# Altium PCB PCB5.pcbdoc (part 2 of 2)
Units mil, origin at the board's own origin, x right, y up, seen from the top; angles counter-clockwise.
Board outline 5683.34 x 2704.79 mil, 4 copper layers (Top Layer, Inner1, Inner2, Bottom Layer); 104 components, 86 nets, 284 pads, 113 vias.
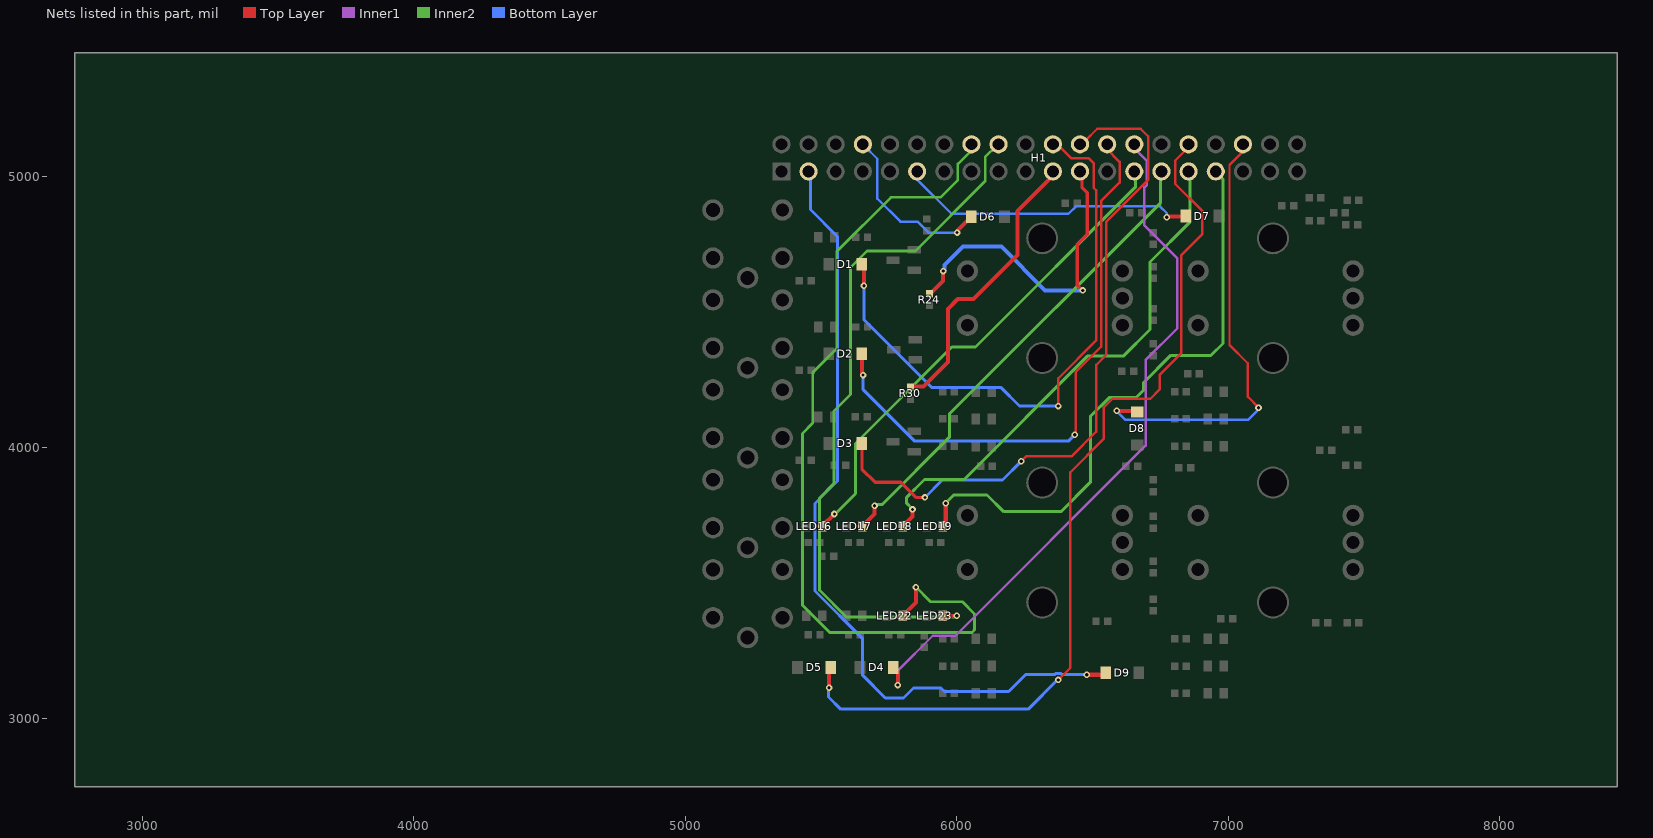
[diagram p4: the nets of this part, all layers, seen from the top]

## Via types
v1: diameter 24.02, hole 12.01, Top Layer to Bottom Layer, 86 vias
v2: diameter 25, hole 12, Top Layer to Bottom Layer, 7 vias
v3: diameter 33, hole 18, Top Layer to Bottom Layer, 6 vias
v4: diameter 25, hole 15, Top Layer to Bottom Layer, 5 vias
v5: diameter 30, hole 15, Top Layer to Bottom Layer, 3 vias
v6: diameter 30, hole 16, Top Layer to Bottom Layer, 3 vias
v7: diameter 28, hole 15, Top Layer to Bottom Layer, 1 vias
v8: diameter 35, hole 18, Top Layer to Bottom Layer, 1 vias
v9: diameter 22, hole 12, Top Layer to Bottom Layer, 1 vias

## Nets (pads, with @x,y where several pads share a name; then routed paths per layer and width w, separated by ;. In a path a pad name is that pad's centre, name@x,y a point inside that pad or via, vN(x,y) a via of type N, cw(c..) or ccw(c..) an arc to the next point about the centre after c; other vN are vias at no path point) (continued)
ROOM3_LED: H1.16 LED22.2 | length 3183.6
  Top Layer w15: LED22.2@5800.47,3380.07 5849.24,3428.84 v1(5849.24,3485.06)
  Inner2 w10: v1@5845.09,3489.42 5902.8,3431.71 6020.54,3431.71 6065.32,3386.93 6065.32,3328.61 6055.32,3318.61 5531.91,3318.61 5431.61,3418.91 5431.61,4051.86 5469.24,4089.49 5469.24,4275.54 5557.61,4363.91 5557.61,4721.82 5757.16,4921.37 5939.92,4921.37 6003.47,4984.92 6003.47,5044.16 6046.1,5086.79 H1.16@6046.1,5115.3
ROOM4_LED: H1.18 LED23.2 | length 2617
  Top Layer w15: LED23.2@5948.77,3380.07 v1(5999.24,3380.06)
  Inner2 w10: v1@5998.07,3375.58 5592.49,3375.58 5493.73,3474.34 5493.73,3814.24 5547.75,3868.26 5547.75,4134.26 5608.43,4194.93 5608.43,4663 5669.39,4723.97 5847.3,4723.97 6104.22,4980.89 6104.22,5069.46 6147.49,5112.73 H1.18@6147.49,5120.64
SINGLE_ROOM_LED: H1.21 R30.1 | length 1062.7
  Top Layer w15: R30.1@5827.41,4224.48 5876.42,4224.48 5966.62,4314.67 5966.62,4510.35 6003.32,4547.04 6061.03,4547.04 6222.71,4708.72 6222.71,4870.8 H1.21@6357.11,5005.2
SINGLE_SPK_LED: H1.23 R24.1 | length 1207
  Top Layer w12: H1.23@6446.98,5017.28 6460.68,5003.57 6460.68,4959.04 6480.71,4939.01 6480.71,4786.01 6443.81,4749.12 6443.81,4598.26 v1(6463.58,4578.49)
  Top Layer w15: R24.1@5899.68,4563.6 5949.49,4613.41 v1@5949.49,4652.94
  Bottom Layer w15: v1@5955.22,4654.39 5955.22,4671.96 6023.04,4739.78 6163.94,4739.78 6325.22,4578.49 v1(6463.58,4578.49)
  other v1: 5950.28,4649.78
SPK1_LED: H1.27 LED16.2 | length 1835.9
  Top Layer w15: LED16.2@5503.77,3710.07 5548.76,3755.06 v1(5549.24,3755.06)
  Inner2 w11: v1@5549.86,3753.01 5626.53,3829.67 5626.53,4014.74 5981.56,4369.78 6068.7,4369.78 6657.2,4958.28 H1.27@6657.2,5015.11
SPK2_LED: H1.29 LED17.2 | length 1772.1
  Top Layer w15: LED17.2@5652.1,3710.07 5696.99,3754.96 v1(5696.99,3785.06)
  Inner2 w11: v1@5694.74,3789.28 5724.09,3789.28 5972.24,4037.43 5972.24,4123.31 6750.79,4901.85 H1.29@6750.79,5013.13
SPK3_LED: H1.31 LED18.2 | length 1905.9
  Top Layer w15: LED18.2@5800.43,3710.07 5836.61,3746.25 v1(5836.61,3772.02)
  Inner2 w11: v1@5832.9,3776.82 5815.11,3794.61 5815.11,3816.62 5880.86,3882.37 6026.8,3882.37 6480.7,4336.28 6613.03,4336.28 6711.56,4434.8 6711.56,4683.35 6858.12,4829.91 H1.31@6858.12,5003.35
SPK4_LED: H1.33 LED19.2 | length 2200.2
  Top Layer w15: LED19.2@5948.77,3710.07 5959.24,3720.54 v1(5959.24,3795.06)
  Inner2 w11: v1@5961.72,3798.71 5988.4,3825.4 6111.14,3825.4 6172.81,3763.73 6383.9,3763.73 6491.82,3871.65 6491.82,4113.84 6563.03,4185.05 6661.8,4185.05 6688.24,4211.48 6688.24,4239.89 6788,4339.65 6936.51,4339.65 6980.05,4383.2 6980.9,4987.59 H1.33@6955.16,5013.33
SW_ALL_ROOM: D1.1 H1.22 | length 2191.5
  Top Layer w9: H1.22@6357.42,5127.5 6359.17,5127.5 6420.62,5066.05 6485.51,5066.05 6503.94,5047.62 6503.94,4956.83 6512.94,4947.83 6512.94,4394.11 6373.81,4254.98 v1(6373.81,4152.52)
  Top Layer w15: D1.1@5650.26,4675.06 5657.64,4667.68 v1(5657.64,4596.25)
  Bottom Layer w11: v1(5657.64,4596.25) 5657.64,4470.61 5906.7,4221.55 6161.48,4221.55 6230.52,4152.52 v1(6373.81,4152.52)
SW_BASS: D8.1 H1.36 | length 1659
  Top Layer w9: H1.36@7050.28,5113.12 7046.32,5109.17 7046.32,5083.06 7004.45,5041.18 7004.45,4377.42 7071.43,4310.44 7071.43,4187.23 v1@7110.76,4147.89
  Top Layer w15: v1(6588.56,4135.05) 6654.97,4135.05 D8.1@6660.51,4129.51
  Bottom Layer w10: v1(6588.56,4135.05) 6621.77,4101.84 7073.2,4101.84 v1@7114.32,4142.95
  other v1: 7111.15,4146.9
SW_CHG_ROOM: D5.1 H1.32 | length 3359.7
  Top Layer w9: v1(6373.7,3143.87) 6417.78,3187.95 6417.78,3908.57 6540.44,4031.23 6540.44,4146.26 6573.98,4179.8 6713.01,4179.8 6747,4213.79 6747,4267.74 6827.03,4347.77 6827.03,4709.08 6904.6,4786.65 6904.6,4871.08 6804.01,4971.67 6804.01,5056.47 6846.93,5099.39 6846.93,5116.31 H1.32@6849.74,5119.12
  Top Layer w15: v1(5529.24,3115.06) 5529.24,3184.04 D5.1@5535.26,3190.06
  Bottom Layer w11: v1@5527.36,3117.78 5527.36,3081.02 5572.42,3035.95 6262.62,3035.95 v1@6371.73,3145.06
SW_CHG_SPK: D4.1 H1.28 | length 2620.8
  Top Layer w15: D4.1@5765.26,3190.06 5782.56,3172.76 v1(5782.56,3125.06)
  Inner1 w9: v1@5775.9,3128.91 5783.81,3136.82 5783.81,3179.11 5911.2,3306.5 5994.7,3306.5 6695.12,4006.92 6695.12,4322.23 6812.39,4439.5 6812.39,4696.68 6690.93,4818.13 6690.93,4957.98 6699.93,4966.98 6699.93,5055.23 6648.43,5106.73 H1.28@6648.43,5119.46 ; v1@5777.42,3124.4 v1@5777.42,3128.91
SW_EXTRA: D9.1 H1.3 | length 2972.4
  Top Layer w15: v1(6478.17,3162.95) 6541.1,3162.95 D9.1@6548.22,3170.06
  Bottom Layer w11: H1.3@5461.13,5002.11 5461.13,4876.3 5560.75,4776.69 5560.75,3877.27 5477.14,3793.67 5477.14,3471.69 5653.19,3295.65 5653.19,3160.93 5736.68,3077.43 5803.67,3077.43 5840.05,3113.81 5941.5,3113.81 5954.45,3100.87 6190.8,3100.87 6252.87,3162.95 6359.55,3162.95 6363.97,3167.36 6383.43,3167.36 6387.85,3162.95 v1(6478.17,3162.95)
SW_SINGLE_ROOM: D3.1 H1.24 | length 2543.7
  Top Layer w9: v1(6237.32,3949.47) 6255.11,3967.26 6422.4,3967.26 6513.46,4058.32 6513.46,4304.14 6549.99,4340.67 6549.99,4830.62 6704.7,4985.34 6704.68,5146.36 6677.08,5173.96 6517.37,5173.96 6472.28,5128.86 H1.24@6459.55,5128.86
  Top Layer w12: D3.1@5650.26,4015.06 5650.26,3920.72 5698.59,3872.39 5792.94,3872.39 5849.25,3816.07 v1(5882.46,3816.07)
  Bottom Layer w11: v1(5882.46,3816.07) 5946.27,3879.88 6167.73,3879.88 v1(6237.32,3949.47)
SW_SINGLE_SPK: D2.1 H1.26 | length 2166.1
  Top Layer w9: v1(6434.56,4047.09) 6437.75,4050.29 6437.75,4277.43 6531.44,4371.12 6531.44,4907.65 6599.78,4975.99 6599.78,5052.37 6549.25,5102.9 6549.25,5115.63 H1.26@6553.77,5120.15
  Top Layer w15: D2.1@5650.26,4345.06 5650.26,4271.15 v1(5654.51,4266.9)
  Bottom Layer w12: v1(5654.51,4266.9) 5654.51,4213.43 5844.3,4023.64 6411.1,4023.64 v1(6434.56,4047.09)
SW_TREB: D7.1 H1.11 | length 1107.8
  Top Layer w15: v1@6778.51,4850.34 6844.92,4850.34 D7.1@6847.29,4852.72
  Bottom Layer w9: H1.11@5848.23,5014.75 5848.23,4992.96 5979.96,4861.23 6411.23,4861.23 6438.26,4888.26 6748.5,4888.26 6773.62,4863.14 v1(6773.62,4848.46)
SW_VOL: D6.1 H1.8 | length 638.6
  Top Layer w15: v1(6000.82,4791.62) 6000.82,4797.66 D6.1@6053.22,4850.06
  Bottom Layer w9: H1.8@5660.13,5110.24 5706.82,5063.55 5706.82,4917.08 5791.76,4832.14 5854.88,4832.14 5895.41,4791.62 v1(6000.82,4791.62)
pads on no net: SW1.6 SW1.7 SW2.6 SW2.7 SW3.6 SW3.7 SW4.6 SW4.7 SW5.4 SW6.4 SW7.4 SW8.4 SW9.4

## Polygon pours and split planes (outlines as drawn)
$2N1617 on Bottom Layer (solid, remove dead copper, pour order 26): 5781.08,3937.85 ccw(c5742.9,3937.58) 5704.71,3937.85 ccw(c5742.9,3938.13)
$2N1617 on Top Layer (solid, remove dead copper, pour order 22): 6808.28,3075.45 ccw(c6764.22,3075.09) 6720.16,3075.45 ccw(c6764.22,3075.81)
$2N1617 on Bottom Layer (solid, remove dead copper, pour order 28): 6808.28,3075.45 ccw(c6764.22,3075.09) 6720.16,3075.45 ccw(c6764.22,3075.81)
$2N1087 on Bottom Layer (solid, remove dead copper, pour order 32): 5964.31,4148.3 ccw(c5938.4,4148.17) 5912.49,4148.3 ccw(c5938.4,4148.42)
$2N1087 on Bottom Layer (solid, remove dead copper, pour order 34): 5763.76,4280.2 ccw(c5734.73,4279.96) 5705.7,4280.2 ccw(c5734.73,4280.43)
GND on Inner1 (solid, remove dead copper): 5142.35,5204.79 7465.18,5204.79 cw(c7465.18,5086.68) 7583.29,5086.68 7583.29,3118.17 cw(c7465.18,3118.17) 7465.18,3000.06 5142.35,3000.06 cw(c5142.35,3118.17) 5024.24,3118.17 5024.24,5086.68 cw(c5142.35,5086.68)
+3.3V on Inner2 (solid, remove dead copper): 5742.35,5204.76 8065.23,5204.76 cw(c8065.23,5086.65) 8183.34,5086.65 8183.34,3118.11 cw(c8065.23,3118.11) 8065.23,3000 5742.35,3000 cw(c5742.35,3118.11) 5624.24,3118.11 5624.24,5086.65 cw(c5742.35,5086.65)
+3.3V on Top Layer (solid, remove dead copper, pour order 0): 6974.24,4310.06 7039.24,4310.06 cw(c7039.24,4300.06) 7049.24,4300.06 7049.24,3930.06 cw(c7039.24,3930.06) 7039.24,3920.06 6974.24,3920.06 cw(c6974.24,3930.06) 6964.24,3930.06 6964.24,4300.06 cw(c6974.24,4300.06)
+5V on Top Layer (solid, remove dead copper, pour order 2): 6124.24,4290.06 6189.24,4290.06 cw(c6189.24,4280.06) 6199.24,4280.06 6199.24,3910.06 cw(c6189.24,3910.06) 6189.24,3900.06 6124.24,3900.06 cw(c6124.24,3910.06) 6114.24,3910.06 6114.24,4280.06 cw(c6124.24,4280.06)
+5V on Top Layer (solid, remove dead copper, pour order 4): 6114.24,3380.06 6179.24,3380.06 cw(c6179.24,3370.06) 6189.24,3370.06 6189.24,3065.06 cw(c6179.24,3065.06) 6179.24,3055.06 6114.24,3055.06 cw(c6114.24,3065.06) 6104.24,3065.06 6104.24,3370.06 cw(c6114.24,3370.06)
+5V on Top Layer (solid, remove dead copper, pour order 6): 6975.37,3335.06 7049.24,3335.06 cw(c7049.24,3325.06) 7059.24,3325.06 7059.24,3044.51 cw(c7049.24,3044.51) 7049.24,3034.51 6975.37,3034.51 cw(c6975.37,3044.51) 6965.37,3044.51 6965.37,3325.06 cw(c6975.37,3325.06)
GND on Top Layer (solid, remove dead copper, pour order 10): 5699.24,3620.06 5954.24,3620.06 cw(c5954.24,3610.06) 5964.24,3610.06 5964.24,3580.06 cw(c5954.24,3580.06) 5954.24,3570.06 5699.24,3570.06 cw(c5699.24,3580.06) 5689.24,3580.06 5689.24,3610.06 cw(c5699.24,3610.06)
GND on Top Layer (solid, remove dead copper, pour order 14): 5509.24,3285.06 5809.24,3285.06 cw(c5809.24,3275.06) 5819.24,3275.06 5819.24,3250.06 cw(c5809.24,3250.06) 5809.24,3240.06 5509.24,3240.06 cw(c5509.24,3250.06) 5499.24,3250.06 5499.24,3275.06 cw(c5509.24,3275.06)
$2N1087 on Bottom Layer (solid, remove dead copper, pour order 30): 5848.96,4195.38 6001.84,4195.38 cw(c6001.84,4185.38) 6011.84,4185.38 6011.84,4156.89 cw(c6001.84,4156.89) 6001.84,4146.89 5848.96,4146.89 cw(c5848.96,4156.89) 5838.96,4156.89 5838.96,4185.38 cw(c5848.96,4185.38)
+5V on Inner2 (solid, remove dead copper): 3118.11,5204.76 5440.99,5204.76 cw(c5440.99,5086.65) 5559.1,5086.65 5559.1,3118.11 cw(c5440.99,3118.11) 5440.99,3000 3118.11,3000 cw(c3118.11,3118.11) 3000,3118.11 3000,5086.65 cw(c3118.11,5086.65)
+5V on Top Layer (solid, remove dead copper, pour order 8): 6989.24,3405.06 6989.24,3305.06 6968.94,3305.06 6898.94,3375.06 6898.94,3399.77 6904.24,3405.06
GND on Top Layer (solid, remove dead copper, pour order 12): 5779.24,3260.06 5799.24,3240.06 5894.24,3240.06 5894.24,3275.11 5864.19,3275.11 5814.24,3325.06 5779.24,3325.06
$2N1617 on Top Layer (solid, remove dead copper, pour order 16): 5774.24,3928.43 5774.24,4065.06 5715.61,4065.06 5695.87,4084.81 5695.87,3923.43 5714.24,3905.06 5750.87,3905.06
$2N1087 on Top Layer (solid, remove dead copper, pour order 18): 5774.73,4262.25 5774.73,4398.88 5716.11,4398.88 5703.74,4411.25 5703.74,4249.87 5714.73,4238.88 5751.37,4238.88
$2N557 on Top Layer (solid, remove dead copper, pour order 20): 5774.24,4593.43 5774.24,4730.06 5715.61,4730.06 5703.25,4742.43 5703.25,4581.05 5714.24,4570.06 5750.87,4570.06
$2N557 on Bottom Layer (solid, remove dead copper, pour order 24): 6071.43,4314.04 6071.43,4262.12 6052.72,4243.41 5961.8,4243.41 5957.85,4247.36 5944.74,4288.17 5984.18,4335.91 6049.56,4335.91

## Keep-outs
Board Outline Layer:
  circle w1: c5162.03,3137.86 r53.15
  circle w10: c5162.03,3137.86 r53.15
  circle w1: c5162.03,5066.99 r53.15
  circle w10: c5162.03,5066.99 r53.15
  circle w1: c7445.5,3137.86 r53.15
  circle w10: c7445.5,3137.86 r53.15
  circle w1: c7445.5,5066.99 r53.15
  circle w10: c7445.5,5066.99 r53.15
  lines w10: 5024.24,3118.17 ccw(c5142.35,3118.17) 5142.35,3000.06 7465.18,3000.06 ccw(c7465.18,3118.17) 7583.29,3118.17 7583.29,5086.68 ccw(c7465.18,5086.68) 7465.18,5204.79 5142.35,5204.79 ccw(c5142.35,5086.68) 5024.24,5086.68 5024.24,3118.17

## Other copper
Top Layer:
  drawing of 246 lines, arcs and shapes, not listed
Inner1:
  region net $2N1087: 6799.68,4145.78 6789.08,4135.17 6787.95,4136.43 6787,4137.66 6785.33,4139.85 6784.44,4140.69 6783.41,4141.29 6782.15,4141.59 6780.59,4141.54 6793.32,4154.27 6793.27,4152.71 6793.57,4151.45 6794.17,4150.42 6795.01,4149.53 6797.2,4147.85 6798.43,4146.91
  region net $2N557: 6856.89,3399.85 6856.89,3384.85 6853.76,3384.64 6850.8,3384.07 6848.06,3383.27 6845.6,3382.35 6841.81,3380.63 6839.93,3379.85 6839.93,3404.85 6841.81,3404.07 6845.6,3402.35 6848.06,3401.43 6850.8,3400.63 6853.76,3400.07
  region net $2N1087: 6763.87,3249.6 6774.48,3238.99 6773.23,3237.87 6771.99,3236.92 6769.81,3235.25 6768.96,3234.36 6768.36,3233.33 6768.06,3232.07 6768.11,3230.51 6755.39,3243.24 6756.95,3243.18 6758.2,3243.48 6759.24,3244.08 6760.13,3244.93 6761.8,3247.11 6762.75,3248.35
  region net $2N1617: 6791.78,4050.52 6779.06,4037.79 6775.93,4040.55 6772.65,4042.87 6769.37,4044.79 6766.26,4046.34 6761.23,4048.45 6758.9,4049.46 6780.12,4070.67 6781.12,4068.34 6783.23,4063.31 6784.78,4060.2 6786.7,4056.92 6789.03,4053.64
  region net $2N1617: 6724.22,3059.14 6721.92,3077.14 6723.94,3077.03 6725.79,3076.75 6729.08,3076.25 6730.52,3076.28 6731.84,3076.65 6733.06,3077.51 6734.17,3078.96 6736.47,3058.09 6735.07,3059.32 6733.73,3059.99 6732.39,3060.23 6731.02,3060.16 6727.97,3059.56 6726.21,3059.27
  region net $2N557: 6807.55,4260.17 6806.32,4245.17 6804.65,4245.26 6803.13,4245.47 6800.46,4245.87 6799.26,4245.86 6798.1,4245.59 6796.96,4244.97 6795.82,4243.89 6797.05,4261.85 6798.05,4260.65 6799.11,4259.92 6800.26,4259.58 6801.5,4259.53 6804.29,4259.88 6805.86,4260.08
  region net CLK_VOL: 6296.07,4881.38 6293.66,4890.38 6296.2,4890.42 6298.56,4890.74 6299.62,4891.1 6300.57,4891.63 6301.39,4892.38 6302.06,4893.39 6304.47,4879.18 6303.6,4879.88 6302.65,4880.41 6300.58,4881.07 6298.35,4881.33
  region net CLK_VOL: 6755.9,4484.85 6755.9,4493.85 6756.99,4494.03 6757.92,4494.53 6759.62,4496.02 6757.08,4481.83 6756.85,4482.68 6756.7,4483.68 6756.44,4484.5 6756.22,4484.75
Inner2:
  region net SPK2_LED: 5711.86,3794.78 5716.92,3783.78 5714.12,3783.98 5711.67,3784.13 5710.63,3783.99 5709.74,3783.59 5709.03,3782.85 5708.51,3781.69 5703.46,3795.18 5704.6,3794.56 5705.61,3794.23 5706.53,3794.13 5707.43,3794.19 5709.37,3794.54
  region net SPK1_LED: 5560.15,3771.07 5566.32,3761.68 5564.47,3760.05 5562.86,3758.66 5562.21,3757.92 5561.71,3757.08 5561.38,3756.08 5561.24,3754.86 5552.79,3766.53 5554.01,3766.31 5555.06,3766.42 5555.98,3766.8 5556.81,3767.42 5558.39,3769.11
  region net ROOM3_LED: 5865.55,3476.03 5858.61,3468.83 5856.89,3470.6 5855.2,3472.11 5854.3,3472.68 5853.33,3473.07 5852.27,3473.26 5851.08,3473.2 5861.15,3483.51 5861.11,3482.33 5861.32,3481.27 5861.72,3480.31 5862.29,3479.41 5863.8,3477.73
  region net ROOM2_LED: 5710.29,3494.44 5713.49,3482.08 5712,3480.81 5710.16,3479.36 5708.47,3477.8 5707.84,3477.02 5707.45,3476.24 5702.93,3489.92 5704.07,3489.34 5705.07,3489.26 5705.96,3489.59 5706.78,3490.25 5708.41,3492.21
  region net ROOM1_LED: 5558.31,3504.64 5565.95,3495.31 5563.97,3493.68 5562.24,3492.4 5561.56,3491.72 5561.05,3490.92 5560.75,3489.93 5560.7,3488.67 5551.39,3499.67 5552.64,3499.54 5553.65,3499.72 5554.49,3500.17 5555.23,3500.84 5556.62,3502.62
  region net ROOM4_LED: 5984.62,3370.58 5979.23,3380.58 5982.03,3380.45 5984.51,3380.47 5985.56,3380.7 5986.45,3381.18 5987.15,3381.97 5987.64,3383.16 5993.02,3369.79 5991.93,3370.35 5990.92,3370.69 5989.01,3370.87 5987,3370.71
  region net SPK4_LED: 5967.13,3811.91 5975.61,3804.83 5973.71,3803.12 5972.06,3801.57 5971.44,3800.75 5971.03,3799.84 5970.86,3798.8 5970.98,3797.58 5960.11,3807.04 5961.33,3807.07 5962.35,3807.34 5963.23,3807.8 5964.01,3808.44 5965.48,3810.05
  region net SPK3_LED: 5820.22,3781.73 5828.65,3788.85 5830.31,3786.99 5831.78,3785.38 5832.57,3784.75 5833.45,3784.28 5834.47,3784.02 5835.68,3783.99 5824.86,3774.48 5824.97,3775.7 5824.8,3776.74 5824.39,3777.65 5823.77,3778.47 5822.12,3780.02
Bottom Layer:
  region net $2N557: 5937.09,3227.77 5923.81,3235.69 5925.96,3238.15 5927.3,3240.32 5928.09,3242.32 5928.58,3244.25 5929.01,3246.23 5929.62,3248.38 5930.68,3250.8 5932.42,3253.6 5952.57,3238.8 5950.54,3236.43 5948.68,3234.82 5946.93,3233.75 5945.21,3232.96 5943.44,3232.21 5941.54,3231.26 5939.45,3229.86
  region net SW_CHG_ROOM: 6362.44,3128 6356.56,3137.67 6358.41,3139.29 6360.02,3140.65 6360.68,3141.38 6361.19,3142.21 6361.54,3143.2 6361.71,3144.42 6369.82,3132.51 6368.6,3132.77 6367.56,3132.68 6366.64,3132.3 6365.8,3131.69 6364.21,3129.98
  region net $1N13924: 6096.11,3758.33 6099.43,3747.33 6097.36,3747.22 6095.31,3746.91 6093.28,3746.41 6091.29,3745.73 6089.33,3744.89 6087.42,3743.89 6083.74,3741.51 6080.31,3738.69 6077.15,3735.55 6074.32,3732.18 6071.87,3728.71 6068.55,3775.84 6071.43,3772.57 6074.42,3769.41 6077.55,3766.45 6080.83,3763.8 6084.3,3761.56 6086.11,3760.63 6087.98,3759.83 6089.91,3759.19 6091.91,3758.72 6093.97,3758.43
  region net $1N13924: 6565.91,3968.31 6557.75,3975.71 6559.64,3977.41 6561.27,3978.94 6561.89,3979.76 6562.32,3980.66 6562.51,3981.7 6562.42,3982.92 6572.99,3973.12 6571.77,3973.12 6570.75,3972.88 6569.86,3972.42 6569.07,3971.8 6567.58,3970.18
  region net CLK_BASS: 6657.67,3471.48 6668.67,3471.48 6668.74,3470.15 6669,3468.85 6669.52,3467.67 6670.38,3466.73 6655.97,3466.73 6656.82,3467.67 6657.34,3468.85 6657.6,3470.15
  region net $2N1087: 5909.36,3181.82 5919.07,3166.08 5916.56,3163.24 5914.89,3160.73 5913.76,3158.45 5912.88,3156.32 5911.95,3154.24 5910.68,3152.12 5908.77,3149.87 5905.94,3147.4 5887.95,3171.4 5891.29,3173.52 5894.17,3174.81 5896.73,3175.57 5899.1,3176.09 5901.42,3176.68 5903.81,3177.63 5906.41,3179.24
  region net $2N1087: 6471.73,3220 6469.97,3238 6473.83,3238.26 6476.8,3238.95 6479.16,3239.94 6481.23,3241.1 6483.3,3242.29 6485.66,3243.38 6488.62,3244.25 6492.47,3244.76 6494.23,3214.81 6490.43,3214.86 6487.47,3215.37 6485.09,3216.19 6482.98,3217.18 6480.88,3218.2 6478.49,3219.1 6475.54,3219.75
  region net SW_EXTRA: 6460.16,3157.45 6460.16,3168.45 6462.67,3168.31 6464.9,3168.23 6465.9,3168.36 6466.85,3168.68 6467.74,3169.26 6468.56,3170.15 6468.56,3155.74 6467.74,3156.63 6466.85,3157.21 6465.9,3157.54 6464.9,3157.66 6462.67,3157.58
  region net $1N15952: 6755.52,3149.27 6755.52,3138.27 6753.01,3138.4 6750.79,3138.48 6749.78,3138.35 6748.83,3138.03 6747.95,3137.45 6747.12,3136.56 6747.12,3150.97 6747.95,3150.08 6748.83,3149.5 6749.78,3149.18 6750.79,3149.05 6753.01,3149.13
  region net SW_SINGLE_ROOM: 5891.31,3832.7 5899.09,3824.92 5897.21,3823.23 5895.58,3821.72 5894.96,3820.92 5894.52,3820.02 5894.3,3818.98 5894.35,3817.77 5884.16,3827.96 5885.37,3827.91 5886.41,3828.13 5887.31,3828.57 5888.11,3829.19 5889.62,3830.82
  region net SW_CHG_ROOM: 5532.86,3096.04 5521.86,3098.3 5522.01,3100.75 5522.17,3102.88 5522.1,3103.86 5521.86,3104.81 5521.39,3105.75 5520.62,3106.7 5534.85,3104.45 5533.83,3103.74 5533.17,3102.93 5532.79,3102 5532.64,3100.98 5532.71,3098.66
  region net $2N6582: 5603.24,3143.07 5615.24,3143.07 5615.01,3140.5 5614.72,3138.31 5614.74,3137.33 5614.99,3136.4 5615.53,3135.52 5616.44,3134.67 5602.03,3134.67 5602.95,3135.52 5603.49,3136.4 5603.73,3137.33 5603.76,3138.31 5603.47,3140.5
  region net $1N15952: 6852.25,3704.1 6843.48,3710.89 6844.88,3712.44 6846.12,3714.11 6847.19,3715.88 6848.12,3717.75 6848.89,3719.7 6849.53,3721.73 6850.43,3725.94 6850.87,3730.31 6850.9,3734.72 6850.59,3739.1 6850,3743.34 6884.38,3710.94 6880.07,3711.35 6875.7,3711.55 6871.35,3711.47 6867.08,3711.03 6862.97,3710.15 6860.99,3709.52 6859.08,3708.76 6857.24,3707.84 6855.48,3706.76 6853.82,3705.52
  region net $2N1087: 5756,4262.15 5741.76,4255.18 5739.56,4257.74 5737.79,4259.94 5736.85,4260.85 5735.75,4261.6 5734.41,4262.16 5732.74,4262.5 5749.9,4272.38 5749.43,4270.72 5749.48,4269.29 5749.97,4268.02 5750.81,4266.86 5751.92,4265.74 5753.21,4264.63
  region net $2N6576: 5160.34,4372.65 5160.34,4360.65 5158.29,4360.55 5156.27,4360.26 5154.28,4359.78 5152.32,4359.14 5148.53,4357.4 5144.91,4355.15 5141.5,4352.48 5138.33,4349.5 5135.41,4346.32 5132.78,4343.03 5132.78,4390.28 5135.41,4386.99 5138.33,4383.8 5141.5,4380.83 5144.91,4378.16 5148.53,4375.91 5152.32,4374.17 5154.28,4373.52 5156.27,4373.05 5158.29,4372.75
  region net $2N6576: 5465.75,4328.08 5457.26,4336.57 5459.25,4338.23 5461,4339.57 5461.67,4340.28 5462.15,4341.11 5462.39,4342.12 5462.35,4343.36 5472.54,4333.18 5471.29,4333.22 5470.29,4332.98 5469.46,4332.5 5468.74,4331.82 5467.4,4330.07
  region net $2N6573: 5160.34,4703.9 5160.34,4691.9 5158.29,4691.8 5156.27,4691.51 5154.28,4691.03 5152.32,4690.39 5148.53,4688.65 5144.91,4686.4 5141.5,4683.73 5138.33,4680.75 5135.41,4677.57 5132.78,4674.28 5132.78,4721.53 5135.41,4718.24 5138.33,4715.05 5141.5,4712.08 5144.91,4709.41 5148.53,4707.16 5152.32,4705.42 5154.28,4704.77 5156.27,4704.3 5158.29,4704
  region net $2N6573: 5465.75,4658.08 5457.26,4666.57 5459.25,4668.23 5461,4669.57 5461.67,4670.28 5462.15,4671.11 5462.39,4672.12 5462.35,4673.36 5472.54,4663.18 5471.29,4663.22 5470.29,4662.98 5469.46,4662.5 5468.74,4661.82 5467.4,4660.07
  region net $2N6578: 5470.75,3998.08 5462.26,4006.57 5464.25,4008.23 5466,4009.57 5466.67,4010.28 5467.15,4011.11 5467.39,4012.12 5467.35,4013.36 5477.54,4003.18 5476.29,4003.22 5475.29,4002.98 5474.46,4002.5 5473.74,4001.82 5472.4,4000.07
  region net $2N6582: 5107.29,3653.01 5095.29,3653.01 5095.19,3654.98 5094.89,3656.75 5094.42,3658.35 5093.77,3659.8 5092.98,3661.12 5092.04,3662.33 5089.78,3664.49 5087.11,3666.44 5084.14,3668.35 5080.95,3670.37 5077.67,3672.66 5124.91,3672.66 5121.62,3670.37 5118.44,3668.35 5115.46,3666.44 5112.8,3664.49 5110.54,3662.33 5109.6,3661.12 5108.8,3659.8 5108.16,3658.35 5107.68,3656.75 5107.39,3654.98
  region net $2N6580: 5348.24,3208.07 5360.24,3208.07 5360.01,3205.5 5359.72,3203.31 5359.74,3202.33 5359.99,3201.4 5360.53,3200.52 5361.44,3199.67 5347.03,3199.67 5347.95,3200.52 5348.49,3201.4 5348.73,3202.33 5348.76,3203.31 5348.47,3205.5
  region net $2N6580: 5151.51,3391.06 5166.1,3379.06 5164.09,3378.96 5162.03,3378.66 5159.93,3378.17 5157.82,3377.51 5155.72,3376.69 5153.64,3375.71 5149.64,3373.36 5145.98,3370.53 5144.32,3368.97 5142.8,3367.33 5141.45,3365.61 5140.27,3363.84 5139.3,3362.02 5138.54,3360.16 5123.95,3405.1 5127.5,3402.48 5130.75,3399.94 5133.84,3397.57 5136.9,3395.45 5140.06,3393.65 5143.46,3392.27 5145.29,3391.76 5147.23,3391.38 5149.3,3391.14
  region net CLK_EXTRA: 7405.14,3412.03 7405.67,3400.03 7403.07,3400.26 7400.86,3400.54 7399.88,3400.51 7398.95,3400.25 7398.09,3399.68 7397.27,3398.74 7396.74,3413.14 7397.62,3412.26 7398.52,3411.74 7399.44,3411.51 7400.42,3411.49 7402.58,3411.79
  region net DT_TREB: 7512.86,4883.16 7509.98,4892.16 7512.55,4892.2 7514.93,4892.5 7515.99,4892.86 7516.93,4893.4 7517.74,4894.17 7518.39,4895.2 7521.27,4881.08 7520.38,4881.75 7519.42,4882.26 7517.35,4882.88 7515.13,4883.12
  region net $2N557: 6196.69,4412.32 6213.7,4401.05 6212.73,4400.48 6211.46,4400.23 6208.54,4400.22 6207.18,4400.22 6206.05,4400.06 6205.31,4399.61 6205.12,4399.25 6205.08,4398.77 6189.96,4408.16 6191.69,4408.95 6193.52,4409.95 6195.24,4411.1
  region net $2N557: 5977.46,4254.09 5969.77,4274.09 5972.54,4273.97 5975,4273.97 5976.08,4274.18 5977.03,4274.63 5977.85,4275.37 5978.52,4276.48 5986.21,4259.47 5985.36,4259.66 5984.64,4259.68 5984.02,4259.54 5983.5,4259.28 5982.64,4258.44 5981.92,4257.36 5981.19,4256.2 5980.3,4255.15 5979.11,4254.39 5978.35,4254.17
  region net $2N1087: 5759.3,4271.8 5748.72,4254.1 5747.05,4255.67 5745.49,4256.93 5744.02,4257.93 5742.62,4258.71 5739.99,4259.75 5737.43,4260.4 5734.82,4260.96 5731.99,4261.78 5728.8,4263.17 5727.03,4264.19 5725.11,4265.48 5744.61,4292.1 5747.76,4289.44 5749.89,4287.01 5751.33,4284.72 5752.4,4282.46 5753.41,4280.14 5754.68,4277.66 5756.54,4274.91
  region net $2N1087: 5902.59,4175.56 ccw(c5924.74,4071.93) 5853.72,4150.58 5710.1,4268.89 5737.38,4304.56 ccw(c8294.67,7754.72) 5891.4,4195.56
  region net $2N1087: 6755.49,4165.23 6769.63,4179.37 6772.72,4176.58 6775.93,4174.18 6779.09,4172.14 6782.07,4170.46 6786.86,4168.11 6789.08,4166.99 6767.86,4145.78 6766.75,4148 6764.39,4152.79 6762.71,4155.76 6760.68,4158.93 6758.28,4162.14
  region net DT_EXTRA: 7363.64,4090.77 7370.89,4096.25 7372.58,4094.65 7374.39,4093.27 7375.36,4092.73 7376.38,4092.33 7377.45,4092.09 7378.58,4092.05 7367.54,4082.79 7367.69,4083.96 7367.58,4085.06 7367.25,4086.11 7366.75,4087.11 7365.34,4088.99
  region net SW_BASS: 6604.84,4125.84 6597.76,4118.77 6596.05,4120.53 6594.37,4122.04 6593.47,4122.61 6592.51,4123.01 6591.45,4123.2 6590.26,4123.16 6600.45,4133.35 6600.4,4132.16 6600.6,4131.1 6601,4130.13 6601.57,4129.24 6603.08,4127.55
  region net SW_BASS: 7108.27,4129.83 7096.93,4132.64 7099.05,4134.55 7100.84,4136.31 7101.43,4137.21 7101.72,4138.17 7101.62,4139.22 7101.07,4140.38 7114.59,4135.4 7113.41,4134.96 7112.47,4134.45 7111.08,4133.2 7109.86,4131.66
  region net DT_BASS: 6692.58,3805 6691.9,3794 6689.41,3794.14 6687.22,3794.23 6686.21,3794.12 6685.26,3793.82 6684.36,3793.27 6683.5,3792.41 6684.17,3806.81 6684.97,3805.88 6685.83,3805.27 6686.77,3804.93 6687.79,3804.79 6690.04,3804.86
  region net DT_BASS: 6957.5,3882.54 6956.65,3893.54 6959.2,3893.4 6961.46,3893.33 6962.47,3893.47 6963.41,3893.82 6964.28,3894.43 6965.06,3895.37 6965.9,3880.98 6965.03,3881.83 6964.12,3882.37 6963.17,3882.67 6962.17,3882.78 6959.98,3882.67
  region net CLK_BASS: 7263.19,3769.62 7255.73,3777.71 7257.59,3779.39 7259.22,3780.88 7259.84,3781.67 7260.29,3782.56 7260.53,3783.59 7260.52,3784.81 7270.39,3774.31 7269.17,3774.39 7268.14,3774.19 7267.23,3773.76 7266.42,3773.14 7264.89,3771.51
  region net SW_SINGLE_ROOM: 6228.47,3932.85 6220.69,3940.63 6222.57,3942.31 6224.2,3943.82 6224.82,3944.63 6225.26,3945.52 6225.48,3946.56 6225.43,3947.77 6235.62,3937.59 6234.4,3937.63 6233.37,3937.41 6232.47,3936.97 6231.67,3936.35 6230.16,3934.72
  region net SW_ALL_ROOM: 6355.8,4147.02 6355.8,4158.02 6358.32,4157.88 6360.54,4157.8 6361.55,4157.93 6362.49,4158.25 6363.38,4158.83 6364.21,4159.72 6364.21,4145.31 6363.38,4146.2 6362.49,4146.78 6361.55,4147.1 6360.54,4147.23 6358.32,4147.15
  region net SW_SINGLE_SPK: 6426.06,4030.12 6417.58,4038.6 6419.57,4040.26 6421.32,4041.6 6421.99,4042.31 6422.47,4043.14 6422.71,4044.15 6422.67,4045.4 6432.86,4035.21 6431.61,4035.25 6430.6,4035.01 6429.78,4034.53 6429.06,4033.85 6427.72,4032.1
  region net SINGLE_SPK_LED: 5947.72,4669.85 5962.72,4663.98 5962.58,4662.87 5962.22,4661.77 5961.22,4659.63 5960.78,4658.59 5960.49,4657.56 5960.47,4656.56 5960.8,4655.57 5947.43,4661.44 5948.61,4661.92 5949.19,4662.59 5949.3,4663.44 5949.1,4664.45 5948.24,4666.92 5947.87,4668.33
  region net $2N1087: 5920.69,4147.36 5920.23,4162.36 5923.43,4162.57 5925.9,4163.14 5927.88,4163.95 5929.61,4164.88 5931.34,4165.83 5933.32,4166.66 5935.78,4167.28 5938.98,4167.56 5939.44,4142.56 5936.26,4142.73 5933.79,4143.25 5931.81,4144.01 5930.07,4144.9 5928.33,4145.8 5926.35,4146.59 5923.88,4147.15
  region net DT_VOL: 6645.71,4730.48 6645.71,4739.48 6648.17,4739.58 6650.57,4740 6651.69,4740.39 6652.72,4740.91 6653.65,4741.6 6654.46,4742.48 6654.46,4727.48 6653.65,4728.35 6652.72,4729.04 6651.69,4729.57 6650.57,4729.95 6648.17,4730.38
  region net SW_ALL_ROOM: 5663.14,4578.24 5652.14,4578.24 5652.27,4580.76 5652.35,4582.98 5652.23,4583.99 5651.9,4584.93 5651.32,4585.82 5650.43,4586.65 5664.84,4586.65 5663.95,4585.82 5663.37,4584.93 5663.05,4583.99 5662.92,4582.98 5663,4580.76
  region net SW_SINGLE_SPK: 5660.51,4248.89 5648.51,4248.89 5648.74,4251.47 5649.03,4253.65 5649,4254.63 5648.76,4255.56 5648.22,4256.44 5647.3,4257.29 5661.71,4257.29 5660.8,4256.44 5660.26,4255.56 5660.01,4254.63 5659.99,4253.65 5660.28,4251.47
  region net SW_TREB: 6769.12,4863.14 6778.12,4863.14 6778.35,4861.78 6778.96,4860.35 6779.83,4859.05 6780.82,4858.07 6766.41,4858.07 6767.41,4859.05 6768.27,4860.35 6768.89,4861.78
  region net SINGLE_SPK_LED: 6445.57,4570.99 6445.57,4585.99 6448.89,4586.19 6452.04,4586.7 6454.96,4587.42 6457.58,4588.25 6461.61,4589.8 6463.58,4590.5 6463.58,4566.48 6461.61,4567.19 6457.58,4568.74 6454.96,4569.57 6452.04,4570.29 6448.89,4570.8
  region net $2N557: 5729.52,4633.36 5744.52,4636.02 5744.34,4632.45 5744.26,4629.29 5744.48,4627.88 5745,4626.6 5745.9,4625.47 5747.27,4624.47 5727.65,4621.81 5728.73,4623.09 5729.4,4624.37 5729.76,4625.68 5729.88,4627.04 5729.72,4629.99
  region net SW_VOL: 5982.81,4787.12 5982.81,4796.12 5985.2,4796.18 5987.49,4796.51 5988.55,4796.84 5989.54,4797.32 5990.43,4797.97 5991.21,4798.82 5991.21,4784.41 5990.43,4785.26 5989.54,4785.91 5988.55,4786.39 5987.49,4786.72 5985.2,4787.05
  region net CLK_VOL: 6294.73,4883.39 6294.73,4892.39 6297.12,4892.45 6299.41,4892.78 6300.47,4893.12 6301.46,4893.59 6302.35,4894.24 6303.13,4895.09 6303.13,4880.68 6302.35,4881.53 6301.46,4882.18 6300.47,4882.66 6299.41,4882.99 6297.12,4883.32
  region net $2N6578: 5160.34,4041.4 5160.34,4029.4 5158.29,4029.3 5156.27,4029.01 5154.28,4028.53 5152.32,4027.89 5148.53,4026.15 5144.91,4023.9 5141.5,4021.23 5138.33,4018.25 5135.41,4015.07 5132.78,4011.78 5132.78,4059.03 5135.41,4055.74 5138.33,4052.55 5141.5,4049.58 5144.91,4046.91 5148.53,4044.66 5152.32,4042.92 5154.28,4042.27 5156.27,4041.8 5158.29,4041.5

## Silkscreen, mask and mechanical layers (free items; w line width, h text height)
Top Silkscreen Layer:
  text "ALL ROOMS" at 5419.24,4827.56 h65
  text "SINGLE ROOM" at 5419.24,4500.06 h65
  text "ROOM1-LIVING" at 6189.24,4170.06 h65
  text "ROOM2-KITCHEN" at 7030.74,4170.06 h65
  text "SINGLE SPK" at 5419.24,4167.56 h65
  text "VOLUME" at 6189.24,4070.06 h65
  text "BASS" at 7030.74,4070.06 h65
  text "Z1-CENTER" at 6189.24,3970.06 h65
  text "Z2-LEFT" at 7030.74,3970.06 h65
  text "SPEAKER SELECT" at 5419.24,3835.06 h65
  text "C" at 5459.24,3740.06 h65
  text "L" at 5607.54,3740.06 h65
  text "R" at 5751.89,3740.06 h65
  text "S" at 5901.89,3740.06 h65
  text "ROOM SELECT" at 5419.24,3502.56 h65
  text "LIV" at 5431.89,3407.56 h65
  text "KIT" at 5578.74,3407.56 h65
  text "BED" at 5723.74,3407.56 h65
  text "OFF" at 5868.74,3407.56 h65
  text "ROOM3-BEDROOM" at 6189.24,3257.56 h65
  text "ROOM4-OFFICE" at 7030.74,3257.56 h65
  text "TREBLE" at 6189.24,3157.56 h65
  text "CUSTOM" at 7030.74,3157.56 h65
  text "Z3-RIGHT" at 6189.24,3062.56 h65
  text "Z4-ANY" at 7030.74,3062.56 h65
  text "SONOS_HAT-ZAMAN-2025" at 5252.68,3007.64 h65
Bottom Silkscreen Layer:
  region: 7070.05,3318.17 7266.9,3318.17 7266.9,3121.32 7070.05,3121.32
Top Solder Mask Layer:
  circle w64.96: c5162.03,3137.86 r85.63
  circle w64.96: c5162.03,5066.99 r85.63
  circle w64.96: c7445.5,3137.86 r85.63
  circle w64.96: c7445.5,5066.99 r85.63
Bottom Solder Mask Layer:
  circle w64.96: c5162.03,3137.86 r85.63
  circle w64.96: c5162.03,5066.99 r85.63
  circle w64.96: c7445.5,3137.86 r85.63
  circle w64.96: c7445.5,5066.99 r85.63
Mechanical Layer:
  circle w1: c5162.03,3137.86 r53.15
  circle w1: c5162.03,5066.99 r53.15
  circle w1: c7445.5,3137.86 r53.15
  circle w1: c7445.5,5066.99 r53.15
